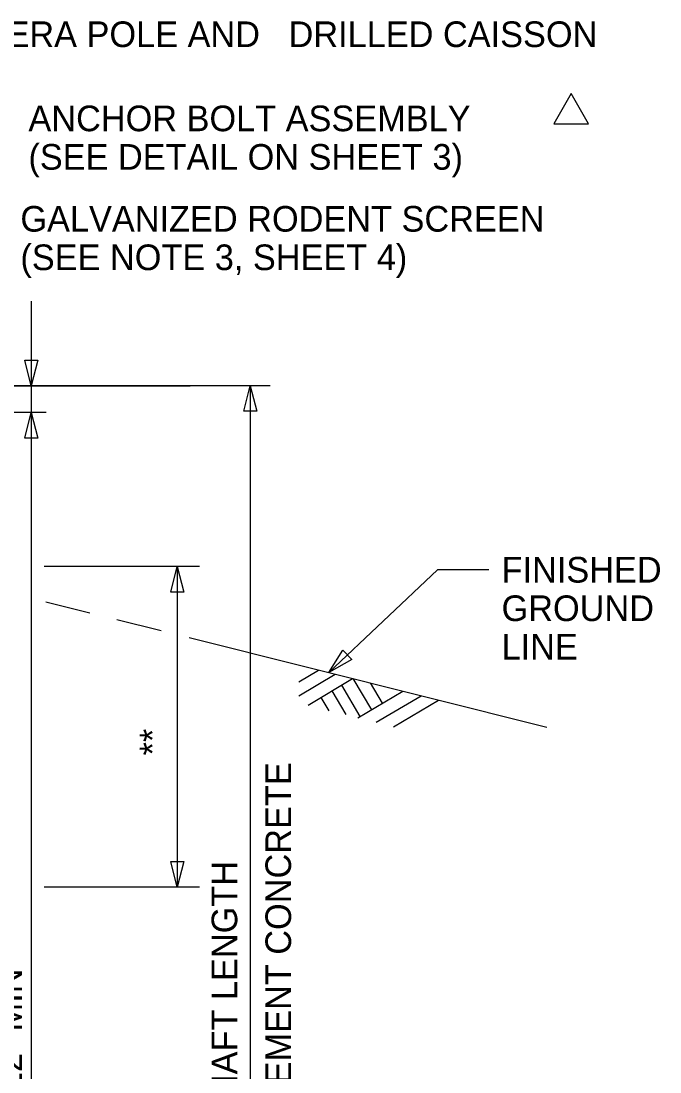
# Model space of a CAD drawing. Extents: x 1299104.6 to 1299141.4, y 239713.3 to 239735.3.
# Drawn here: x 1299112.107 to 1299115.096, y 239719.15 to 239724.067 of the extents above; entities that cross this region are included whole.
import ezdxf

# ---------------------------------------------------------------- set-up
doc = ezdxf.new("R2010")
doc.units = 0
for name, color, linetype in [('DIM TXT', 7, 'Continuous'), ('Level 3', 7, 'Continuous'), ('Level 8', 7, 'Continuous')]:
    doc.layers.add(name, color=color, linetype=linetype)

msp = doc.modelspace()

# ---------------------------------------------------------------- linework, layer by layer
at = {"layer": 'DIM TXT'}
msp.add_lwpolyline([(1299114.5994, 239723.5862), (1299114.7618, 239723.5862), (1299114.6806, 239723.7268)], close=True, dxfattribs=at)
at = {"layer": 'Level 3'}
for p, q in [((1299112.2234, 239721.3494), (1299112.4287, 239721.2981)), ((1299112.5556, 239721.2664), (1299112.7627, 239721.2146)), ((1299112.8928, 239721.1821), (1299114.5665, 239720.7636))]:
    msp.add_line(p, q, dxfattribs=at)
at = {"layer": 'Level 8'}
for p, q in [((1299112.1548, 239722.7556), (1299112.1548, 239716.5612)), ((1299113.2721, 239722.3606), (1299111.6408, 239722.3606)), ((1299112.0547, 239722.3606), (1299112.8979, 239722.3606)), ((1299113.1795, 239722.3606), (1299113.1795, 239716.8606)), ((1299112.2238, 239722.2356), (1299111.6408, 239722.2356)), ((1299112.942, 239721.5146), (1299112.2149, 239721.5146)), ((1299112.8379, 239721.5146), (1299112.8379, 239720.0146)), ((1299113.5466, 239721.0186), (1299114.055, 239721.4994)), ((1299114.295, 239721.4994), (1299114.055, 239721.4994)), ((1299113.4067, 239720.9758), (1299113.4983, 239721.0303)), ((1299113.4067, 239720.9094), (1299113.577, 239721.0107)), ((1299113.4502, 239720.8665), (1299113.6583, 239720.9903)), ((1299113.6059, 239720.9592), (1299113.6924, 239720.8136)), ((1299113.6592, 239720.9901), (1299113.7461, 239720.8441)), ((1299113.7399, 239720.9699), (1299113.7961, 239720.8753)), ((1299113.51, 239720.902), (1299113.5475, 239720.8389)), ((1299113.5607, 239720.9323), (1299113.6265, 239720.8217)), ((1299113.6831, 239720.8073), (1299113.8924, 239720.9318)), ((1299113.7686, 239720.7856), (1299113.9783, 239720.9103)), ((1299113.8496, 239720.765), (1299114.0596, 239720.89)), ((1299112.942, 239720.0146), (1299112.2149, 239720.0146))]:
    msp.add_line(p, q, dxfattribs=at)
for points in [[(1299112.1848, 239722.4806), (1299112.1548, 239722.3606), (1299112.1248, 239722.4806)], [(1299113.1495, 239722.2406), (1299113.1795, 239722.3606), (1299113.2095, 239722.2406)], [(1299112.1248, 239722.1156), (1299112.1548, 239722.2356), (1299112.1848, 239722.1156)], [(1299112.8079, 239721.3946), (1299112.8379, 239721.5146), (1299112.8679, 239721.3946)], [(1299113.6544, 239721.0793), (1299113.5466, 239721.0186), (1299113.6131, 239721.1229)], [(1299112.8679, 239720.1346), (1299112.8379, 239720.0146), (1299112.8079, 239720.1346)]]:
    msp.add_lwpolyline(points, close=True, dxfattribs=at)

# ---------------------------------------------------------------- texts
at = {"layer": 'DIM TXT'}
for s, p in [('  CCTV CAMERA POLE AND   DRILLED CAISSON', (1299111.1115, 239723.9449)), ('ANCHOR BOLT ASSEMBLY', (1299112.1413, 239723.5511)), ('(SEE DETAIL ON SHEET 3)', (1299112.1413, 239723.3711)), ('GALVANIZED RODENT SCREEN', (1299112.1037, 239723.0812)), ('(SEE NOTE 3, SHEET 4)', (1299112.1037, 239722.9012)), ('FINISHED', (1299114.355, 239721.4394)), ('GROUND', (1299114.355, 239721.2594)), ('LINE', (1299114.355, 239721.0794))]:
    msp.add_text(s, height=0.12, dxfattribs=at).set_placement(p)
for s, p in [('**', (1299112.7822, 239720.6308)), ('CLASS A CEMENT CONCRETE', (1299113.3701, 239718.2538)), ('SHAFT LENGTH', (1299113.1184, 239718.9156)), ('#4@12" MIN', (1299112.1118, 239718.7184))]:
    msp.add_text(s, height=0.12, rotation=90, dxfattribs=at).set_placement(p)

doc.saveas('drawing.dxf')
